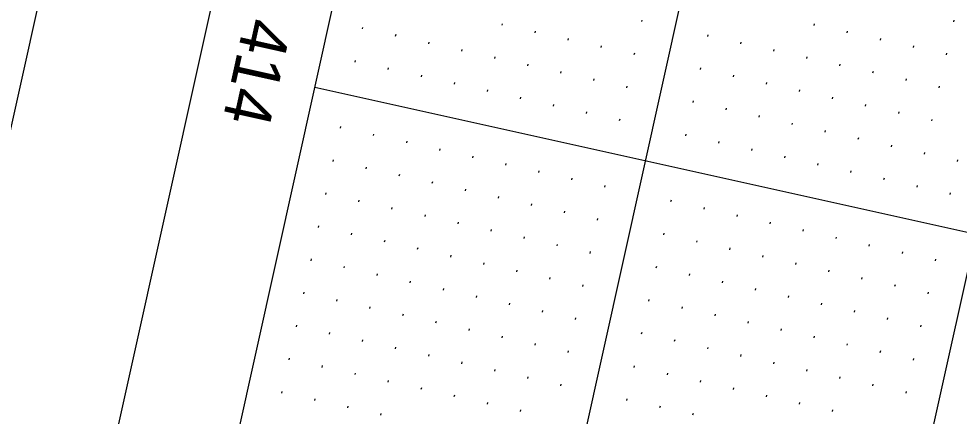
# Model space of a CAD drawing. Extents: x 2149268 to 2150830, y 142155 to 144285.
# Drawn here: x 2149580.1 to 2149719, y 143499.6 to 143558.2 of the extents above; entities that cross this region are included whole.
import ezdxf

# ---------------------------------------------------------------- set-up
doc = ezdxf.new("R2010")
doc.units = 0
for name, color, linetype in [('SHT_Plan_Profile_Sheet_Sta_Txt', 7, 'Continuous'), ('SHT_Plot_Shape_Half', 7, 'Continuous'), ('SHT_Profile_Grid_Major', 7, 'Continuous'), ('SHT_Profile_Grid_Minor', 7, 'Continuous'), ('SHT_Sheet_Border', 7, 'Continuous')]:
    doc.layers.add(name, color=color, linetype=linetype)

msp = doc.modelspace()

# ---------------------------------------------------------------- linework, layer by layer
at = {"layer": 'SHT_Plot_Shape_Half'}
msp.add_lwpolyline([(2150772.24, 143840.86), (2150403.25, 142181.39), (2149329.47, 142420.15), (2149698.47, 144079.62)], close=True, dxfattribs=at)
at = {"layer": 'SHT_Profile_Grid_Major'}
for p, q in [((2149767.6, 143964.37), (2149425.74, 142426.92)), ((2149816.41, 143953.52), (2149474.54, 142416.07)), ((2149623.83, 143548.15), (2150067.98, 143449.39))]:
    msp.add_line(p, q, dxfattribs=at)
at = {"layer": 'SHT_Profile_Grid_Minor'}
for p, q in [((2149651.52, 143557.49), (2149651.46, 143557.25)), ((2149672.12, 143558.03), (2149672.07, 143557.79)), ((2149697.61, 143557.49), (2149697.56, 143557.24)), ((2149718.22, 143558.03), (2149718.17, 143557.78)), ((2149630.91, 143556.95), (2149630.85, 143556.71)), ((2149635.79, 143555.87), (2149635.73, 143555.62)), ((2149656.4, 143556.41), (2149656.34, 143556.16)), ((2149681.89, 143555.86), (2149681.83, 143555.62)), ((2149702.49, 143556.4), (2149702.44, 143556.16)), ((2149640.67, 143554.78), (2149640.61, 143554.54)), ((2149661.28, 143555.32), (2149661.22, 143555.08)), ((2149686.77, 143554.78), (2149686.71, 143554.53)), ((2149707.37, 143555.32), (2149707.32, 143555.07)), ((2149645.55, 143553.7), (2149645.49, 143553.45)), ((2149666.16, 143554.24), (2149666.1, 143553.99)), ((2149671.04, 143553.15), (2149670.98, 143552.91)), ((2149691.65, 143553.69), (2149691.59, 143553.45)), ((2149712.26, 143554.23), (2149712.2, 143553.99)), ((2149717.14, 143553.14), (2149717.08, 143552.9)), ((2149629.82, 143552.07), (2149629.77, 143551.83)), ((2149650.43, 143552.61), (2149650.38, 143552.37)), ((2149696.53, 143552.61), (2149696.47, 143552.36)), ((2149634.7, 143550.99), (2149634.65, 143550.74)), ((2149655.31, 143551.53), (2149655.26, 143551.28)), ((2149660.19, 143550.44), (2149660.14, 143550.2)), ((2149680.8, 143550.98), (2149680.75, 143550.74)), ((2149701.41, 143551.52), (2149701.35, 143551.28)), ((2149706.29, 143550.43), (2149706.23, 143550.19)), ((2149639.58, 143549.9), (2149639.53, 143549.66)), ((2149665.07, 143549.36), (2149665.02, 143549.11)), ((2149685.68, 143549.89), (2149685.63, 143549.65)), ((2149711.17, 143549.35), (2149711.12, 143549.11)), ((2149644.46, 143548.82), (2149644.41, 143548.57)), ((2149649.34, 143547.73), (2149649.29, 143547.49)), ((2149669.95, 143548.27), (2149669.9, 143548.03)), ((2149690.56, 143548.81), (2149690.51, 143548.57)), ((2149695.44, 143547.72), (2149695.39, 143547.48)), ((2149716.05, 143548.26), (2149716, 143548.02)), ((2149654.23, 143546.65), (2149654.17, 143546.4)), ((2149679.71, 143546.1), (2149679.66, 143545.86)), ((2149700.32, 143546.64), (2149700.27, 143546.4)), ((2149659.11, 143545.56), (2149659.05, 143545.32)), ((2149684.6, 143545.01), (2149684.54, 143544.77)), ((2149705.2, 143545.55), (2149705.15, 143545.31)), ((2149663.99, 143544.47), (2149663.93, 143544.23)), ((2149668.87, 143543.39), (2149668.81, 143543.15)), ((2149689.48, 143543.93), (2149689.42, 143543.68)), ((2149710.08, 143544.47), (2149710.03, 143544.22)), ((2149714.97, 143543.38), (2149714.91, 143543.14)), ((2149627.65, 143542.31), (2149627.6, 143542.07)), ((2149694.36, 143542.84), (2149694.3, 143542.6)), ((2149632.53, 143541.22), (2149632.48, 143540.98)), ((2149678.63, 143541.22), (2149678.58, 143540.97)), ((2149699.24, 143541.76), (2149699.18, 143541.51)), ((2149704.12, 143540.67), (2149704.06, 143540.43)), ((2149637.41, 143540.14), (2149637.36, 143539.9)), ((2149683.51, 143540.13), (2149683.46, 143539.89)), ((2149709, 143539.59), (2149708.95, 143539.34)), ((2149642.29, 143539.05), (2149642.24, 143538.81)), ((2149647.17, 143537.97), (2149647.12, 143537.72)), ((2149688.39, 143539.05), (2149688.34, 143538.8)), ((2149693.27, 143537.96), (2149693.22, 143537.72)), ((2149713.88, 143538.5), (2149713.83, 143538.26)), ((2149626.57, 143537.43), (2149626.51, 143537.18)), ((2149652.05, 143536.88), (2149652, 143536.64)), ((2149698.15, 143536.88), (2149698.1, 143536.63)), ((2149718.76, 143537.42), (2149718.71, 143537.17)), ((2149631.45, 143536.34), (2149631.39, 143536.1)), ((2149636.33, 143535.26), (2149636.27, 143535.01)), ((2149656.94, 143535.8), (2149656.88, 143535.55)), ((2149703.03, 143535.79), (2149702.98, 143535.55)), ((2149641.21, 143534.17), (2149641.15, 143533.93)), ((2149661.82, 143534.71), (2149661.76, 143534.47)), ((2149666.7, 143533.63), (2149666.64, 143533.38)), ((2149707.91, 143534.71), (2149707.86, 143534.46)), ((2149712.79, 143533.62), (2149712.74, 143533.38)), ((2149625.48, 143532.55), (2149625.43, 143532.3)), ((2149646.09, 143533.09), (2149646.03, 143532.84)), ((2149717.68, 143532.54), (2149717.62, 143532.29)), ((2149630.36, 143531.46), (2149630.31, 143531.22)), ((2149650.97, 143532), (2149650.92, 143531.76)), ((2149655.85, 143530.92), (2149655.8, 143530.67)), ((2149676.46, 143531.46), (2149676.4, 143531.21)), ((2149635.24, 143530.38), (2149635.19, 143530.13)), ((2149660.73, 143529.83), (2149660.68, 143529.59)), ((2149681.34, 143530.37), (2149681.29, 143530.13)), ((2149640.12, 143529.29), (2149640.07, 143529.05)), ((2149645, 143528.21), (2149644.95, 143527.96)), ((2149665.61, 143528.75), (2149665.56, 143528.5)), ((2149686.22, 143529.29), (2149686.17, 143529.04)), ((2149691.1, 143528.2), (2149691.05, 143527.96)), ((2149624.4, 143527.67), (2149624.34, 143527.42)), ((2149649.88, 143527.12), (2149649.83, 143526.88)), ((2149695.98, 143527.12), (2149695.93, 143526.87)), ((2149629.28, 143526.58), (2149629.22, 143526.34)), ((2149634.16, 143525.5), (2149634.1, 143525.25)), ((2149654.77, 143526.04), (2149654.71, 143525.79)), ((2149675.37, 143526.58), (2149675.32, 143526.33)), ((2149680.25, 143525.49), (2149680.2, 143525.25)), ((2149700.86, 143526.03), (2149700.81, 143525.79)), ((2149639.04, 143524.41), (2149638.98, 143524.17)), ((2149659.65, 143524.95), (2149659.59, 143524.71)), ((2149685.14, 143524.41), (2149685.08, 143524.16)), ((2149705.74, 143524.95), (2149705.69, 143524.7)), ((2149623.31, 143522.79), (2149623.26, 143522.54)), ((2149643.92, 143523.33), (2149643.86, 143523.08)), ((2149664.53, 143523.87), (2149664.47, 143523.62)), ((2149690.02, 143523.32), (2149689.96, 143523.08)), ((2149710.62, 143523.86), (2149710.57, 143523.62)), ((2149715.51, 143522.77), (2149715.45, 143522.53)), ((2149628.19, 143521.7), (2149628.14, 143521.46)), ((2149648.8, 143522.24), (2149648.74, 143522)), ((2149653.68, 143521.16), (2149653.63, 143520.91)), ((2149674.29, 143521.7), (2149674.23, 143521.45)), ((2149694.9, 143522.24), (2149694.84, 143521.99)), ((2149699.78, 143521.15), (2149699.72, 143520.91)), ((2149633.07, 143520.62), (2149633.02, 143520.37)), ((2149658.56, 143520.07), (2149658.51, 143519.83)), ((2149679.17, 143520.61), (2149679.11, 143520.37)), ((2149704.66, 143520.06), (2149704.6, 143519.82)), ((2149637.95, 143519.53), (2149637.9, 143519.29)), ((2149642.83, 143518.45), (2149642.78, 143518.2)), ((2149663.44, 143518.99), (2149663.39, 143518.74)), ((2149684.05, 143519.52), (2149684, 143519.28)), ((2149688.93, 143518.44), (2149688.88, 143518.2)), ((2149709.54, 143518.98), (2149709.48, 143518.74)), ((2149622.22, 143517.91), (2149622.17, 143517.66)), ((2149647.71, 143517.36), (2149647.66, 143517.12)), ((2149693.81, 143517.35), (2149693.76, 143517.11)), ((2149714.42, 143517.89), (2149714.37, 143517.65)), ((2149627.11, 143516.82), (2149627.05, 143516.58)), ((2149631.99, 143515.74), (2149631.93, 143515.49)), ((2149652.59, 143516.27), (2149652.54, 143516.03)), ((2149673.2, 143516.81), (2149673.15, 143516.57)), ((2149678.08, 143515.73), (2149678.03, 143515.49)), ((2149698.69, 143516.27), (2149698.64, 143516.02)), ((2149636.87, 143514.65), (2149636.81, 143514.41)), ((2149657.48, 143515.19), (2149657.42, 143514.95)), ((2149682.96, 143514.64), (2149682.91, 143514.4)), ((2149703.57, 143515.18), (2149703.52, 143514.94)), ((2149621.14, 143513.03), (2149621.08, 143512.78)), ((2149641.75, 143513.56), (2149641.69, 143513.32)), ((2149662.36, 143514.1), (2149662.3, 143513.86)), ((2149687.85, 143513.56), (2149687.79, 143513.31)), ((2149708.45, 143514.1), (2149708.4, 143513.85)), ((2149713.33, 143513.01), (2149713.28, 143512.77)), ((2149626.02, 143511.94), (2149625.97, 143511.7)), ((2149646.63, 143512.48), (2149646.57, 143512.24)), ((2149651.51, 143511.39), (2149651.45, 143511.15)), ((2149672.12, 143511.93), (2149672.06, 143511.69)), ((2149692.73, 143512.47), (2149692.67, 143512.23)), ((2149697.61, 143511.39), (2149697.55, 143511.14)), ((2149630.9, 143510.85), (2149630.85, 143510.61)), ((2149656.39, 143510.31), (2149656.34, 143510.06)), ((2149677, 143510.85), (2149676.94, 143510.6)), ((2149702.49, 143510.3), (2149702.43, 143510.06)), ((2149635.78, 143509.77), (2149635.73, 143509.53)), ((2149640.66, 143508.68), (2149640.61, 143508.44)), ((2149661.27, 143509.22), (2149661.22, 143508.98)), ((2149681.88, 143509.76), (2149681.83, 143509.52)), ((2149686.76, 143508.68), (2149686.71, 143508.43)), ((2149707.37, 143509.22), (2149707.31, 143508.97)), ((2149620.05, 143508.14), (2149620, 143507.9)), ((2149645.54, 143507.6), (2149645.49, 143507.35)), ((2149691.64, 143507.59), (2149691.59, 143507.35)), ((2149712.25, 143508.13), (2149712.2, 143507.89)), ((2149624.93, 143507.06), (2149624.88, 143506.81)), ((2149629.82, 143505.97), (2149629.76, 143505.73)), ((2149650.42, 143506.51), (2149650.37, 143506.27)), ((2149671.03, 143507.05), (2149670.98, 143506.81)), ((2149675.91, 143505.97), (2149675.86, 143505.72)), ((2149696.52, 143506.51), (2149696.47, 143506.26)), ((2149634.7, 143504.89), (2149634.64, 143504.64)), ((2149655.3, 143505.43), (2149655.25, 143505.18)), ((2149680.79, 143504.88), (2149680.74, 143504.64)), ((2149701.4, 143505.42), (2149701.35, 143505.18)), ((2149618.97, 143503.26), (2149618.91, 143503.02)), ((2149639.58, 143503.8), (2149639.52, 143503.56)), ((2149660.19, 143504.34), (2149660.13, 143504.1)), ((2149685.67, 143503.8), (2149685.62, 143503.55)), ((2149706.28, 143504.34), (2149706.23, 143504.09)), ((2149711.16, 143503.25), (2149711.11, 143503.01)), ((2149623.85, 143502.18), (2149623.8, 143501.93)), ((2149644.46, 143502.72), (2149644.4, 143502.47)), ((2149669.95, 143502.17), (2149669.89, 143501.93)), ((2149690.56, 143502.71), (2149690.5, 143502.47)), ((2149628.73, 143501.09), (2149628.68, 143500.85)), ((2149649.34, 143501.63), (2149649.28, 143501.39)), ((2149654.22, 143500.55), (2149654.17, 143500.3)), ((2149674.83, 143501.09), (2149674.77, 143500.84)), ((2149695.44, 143501.63), (2149695.38, 143501.38)), ((2149700.32, 143500.54), (2149700.26, 143500.3)), ((2149633.61, 143500.01), (2149633.56, 143499.76)), ((2149679.71, 143500), (2149679.65, 143499.76))]:
    msp.add_line(p, q, dxfattribs=at)
at = {"layer": 'SHT_Sheet_Border'}
msp.add_line((2149718.79, 143975.22), (2149433.9, 142694.01), dxfattribs=at)
msp.add_lwpolyline([(2150726.67, 143751.11), (2150384.81, 142213.66), (2149359.84, 142441.57), (2149701.71, 143979.02)], close=True, dxfattribs=at)

# ---------------------------------------------------------------- texts
at = {"layer": 'SHT_Plan_Profile_Sheet_Sta_Txt'}
msp.add_text('414', height=7, rotation=257.4638, dxfattribs=at).set_placement((2149613.61, 143558.65))

doc.saveas('drawing.dxf')
